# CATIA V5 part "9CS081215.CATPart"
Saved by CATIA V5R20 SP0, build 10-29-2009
Part number: 9CS081215
Revision: ANY
Definition: UNKNOWN
Nomenclature: 9CS081215
Source: Unknown
Bounding box of the stored display mesh (mm): x -5.85 to 5.85, y -7.5 to 7.5, z -6 to 6
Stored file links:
  C:\Users\Utente\Desktop\IO LAVORO\3D X SITO CF\CUMSA\3D files PW\pw081030\pw081030_ejection\9CS081215.CATPart
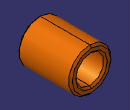
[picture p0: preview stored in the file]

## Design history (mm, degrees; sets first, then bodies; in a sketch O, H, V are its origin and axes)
Body1 "Revolución1" (main body)
  Solid1: solid without history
